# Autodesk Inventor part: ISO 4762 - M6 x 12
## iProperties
Library Location: C:\Program Files\Autodesk\Inventor 6\content
Library: local
SubLibrary: ISO
Family: 13
Member: 590
Member Major Revision: 1
Member Minor Revision: 1
Comments: To add or edit properties for Autodesk Inventor files, use iProperties.
Created: 2003-05
Part Number: ISO 4762 - M6 x 12
Vendor: Autodesk Inc.
Document SubType Name: Modeling
Designer: Philippe
Description: Vis cylindrique à six pans creux
Standard: ISO 4762 M6 x 12
Alert: To add or edit properties for Autodesk Inventor files, use iProperties.
Control State: 0
Master: False
Checked Out: False
Shininess: 64.0
Length Units: 11269
Angle Units: 11279
Time Units: 11290
Mass Units: 11283
Length Display Precision: 3
Angle Display Precision: 2
Compacted: True
EGR: 1
Density: 0.0
Volumn: 0.0
Area: 0.0
PropertySet Name: Model Information
Author: Philippe
Revision Number: 1
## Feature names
1. Corps [Revolution]
2. Fente [Extrusion]
3. Congé1 [Fillet]
4. Chanfrein1 [Chamfer]
